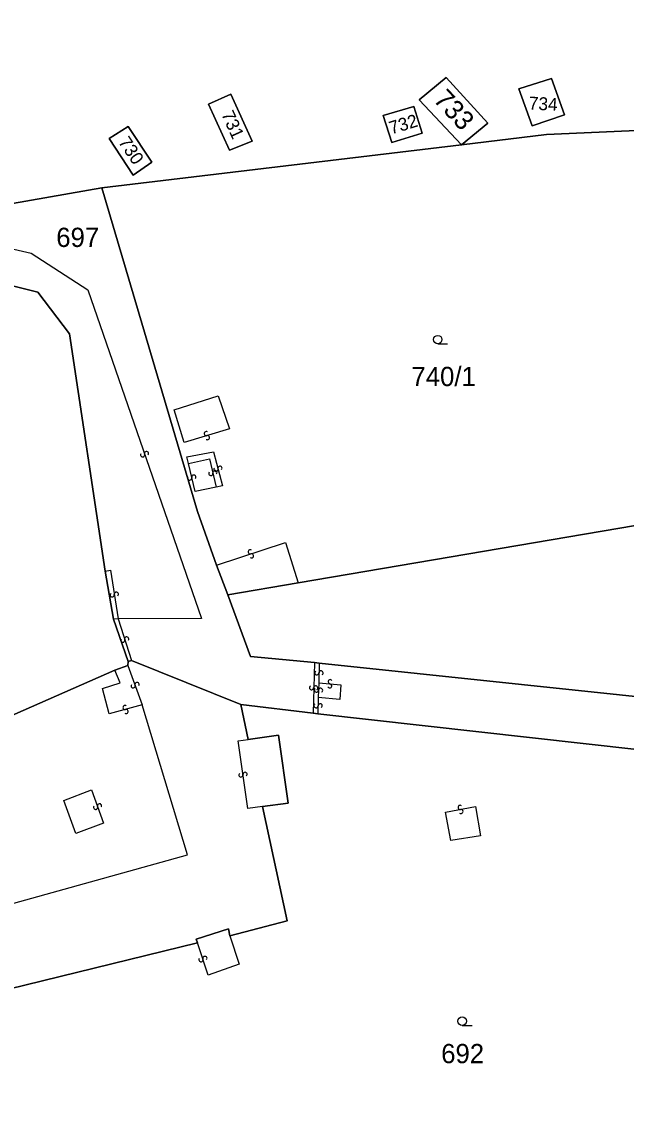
# Model space of a CAD drawing. Extents: x -600309 to -598967, y -1161267 to -1160292.
# Drawn here: x -599586.3 to -599532.9, y -1160977.1 to -1160881.2 of the extents above; entities that cross this region are included whole.
import ezdxf

# ---------------------------------------------------------------- set-up
doc = ezdxf.new("R2010")
doc.units = 0
for name, color, linetype in [('Level 1', 7, 'Continuous'), ('Level 13', 7, 'Continuous'), ('Level 3', 7, 'Continuous'), ('Level 4', 7, 'Continuous'), ('Level 5', 7, 'Continuous'), ('Level 60', 7, 'Continuous')]:
    doc.layers.add(name, color=color, linetype=linetype)

msp = doc.modelspace()

# ---------------------------------------------------------------- linework, layer by layer
at = {"layer": 'Level 1'}
for points in [[(-599547.45, -1160892.09), (-599551.17, -1160888.12), (-599548.78, -1160886.13), (-599545.11, -1160890.17), (-599547.45, -1160892.09)], [(-599542.37, -1160887.15), (-599539.48, -1160886.23), (-599538.32, -1160889.44), (-599541.2, -1160890.42), (-599542.37, -1160887.15)], [(-599569.81, -1160888.5), (-599567.83, -1160887.62), (-599565.94, -1160891.75), (-599567.94, -1160892.55), (-599569.81, -1160888.5)], [(-599554.37, -1160889.51), (-599551.65, -1160888.7), (-599550.92, -1160891.06), (-599553.6, -1160891.87), (-599554.37, -1160889.51)], [(-599578.59, -1160891.52), (-599576.92, -1160890.46), (-599574.82, -1160893.63), (-599576.47, -1160894.77), (-599578.59, -1160891.52)], [(-599521.99, -1160890.39), (-599539.93, -1160891.17), (-599547.45, -1160892.09)], [(-599579.23, -1160895.89), (-599547.45, -1160892.09)], [(-599627.26, -1160901.81), (-599623.88, -1160902.01), (-599610.7, -1160901.38), (-599579.23, -1160895.89)], [(-599579.23, -1160895.89), (-599570.78, -1160924.47), (-599569.11, -1160929.21)], [(-599603.7, -1160903.64), (-599590.9, -1160903.6), (-599584.9, -1160905.11), (-599582.1, -1160908.78), (-599578.94, -1160929.75)], [(-599516.72, -1160923.57), (-599524.58, -1160924.44), (-599561.87, -1160930.78)], [(-599578.94, -1160929.75), (-599578.2, -1160933.98)], [(-599569.11, -1160929.21), (-599568.09, -1160931.83)], [(-599561.87, -1160930.78), (-599568.09, -1160931.83)], [(-599568.09, -1160931.83), (-599566.1, -1160937.3), (-599560.45, -1160937.81)], [(-599578.2, -1160933.98), (-599576.9, -1160937.73)], [(-599576.9, -1160937.73), (-599576.62, -1160937.63)], [(-599576.62, -1160937.63), (-599566.95, -1160941.53)], [(-599626.19, -1160957.49), (-599625.56, -1160959.35), (-599578.08, -1160938.49)], [(-599578.08, -1160938.49), (-599576.93, -1160938.08)], [(-599576.93, -1160938.08), (-599576.9, -1160937.73)], [(-599560.45, -1160937.81), (-599560.03, -1160937.87)], [(-599560.03, -1160937.87), (-599489, -1160945.35), (-599487.6, -1160945.48)], [(-599566.3, -1160944.61), (-599566.95, -1160941.53)], [(-599566.95, -1160941.53), (-599560.56, -1160942.31)], [(-599560.56, -1160942.31), (-599560.13, -1160942.37)], [(-599560.13, -1160942.37), (-599489.23, -1160950.29)], [(-599565.04, -1160950.54), (-599562.75, -1160950.25), (-599563.61, -1160944.23), (-599566.3, -1160944.61)], [(-599567.91, -1160961.97), (-599562.84, -1160960.63), (-599565.04, -1160950.54)], [(-599570.78, -1160962.58), (-599570.9, -1160962.27), (-599568.04, -1160961.36), (-599567.91, -1160961.97)], [(-599634.03, -1160961.92), (-599630.1, -1160977.09), (-599570.78, -1160962.58)]]:
    msp.add_lwpolyline(points, dxfattribs=at)
at = {"layer": 'Level 13'}
for centre, start, end in [((-599570.012, -1160917.603), 53.85752, 286.44752), ((-599569.909, -1160917.957), 234.07198, 106.16998), ((-599575.634, -1160919.479), 146.20637, 18.79637), ((-599575.285, -1160919.361), 326.42083, 198.51882), ((-599571.111, -1160921.439), 320.37294, 192.96294), ((-599569.599, -1160921.121), 140.21983, 12.80983), ((-599569.24, -1160921.04), 320.43428, 192.53228), ((-599569.148, -1160920.757), 142.13739, 14.72739), ((-599568.791, -1160920.664), 322.35185, 194.44984), ((-599571.47, -1160921.521), 140.58739, 12.68539), ((-599566.115, -1160928.044), 55.35565, 287.45365), ((-599566.004, -1160928.395), 235.1412, 107.7312), ((-599578.322, -1160931.848), 136.01455, 8.60455), ((-599577.957, -1160931.793), 316.229, 188.327), ((-599577.395, -1160935.856), 145.16952, 17.75952), ((-599577.044, -1160935.745), 325.38398, 197.48197), ((-599560.224, -1160938.738), 126.82899, 359.41899), ((-599559.856, -1160938.743), 307.04345, 179.14145), ((-599576.126, -1160939.759), 327.27648, 199.37448), ((-599559.05, -1160939.517), 31.77913, 263.87713), ((-599576.473, -1160939.882), 147.06203, 19.65203), ((-599560.694, -1160940.055), 125.75799, 358.34799), ((-599560.326, -1160940.066), 305.97245, 178.07045), ((-599560.264, -1160940.258), 123.66364, 356.25364), ((-599559.896, -1160940.283), 303.87809, 175.97609), ((-599559.089, -1160939.883), 211.56468, 84.15468), ((-599560.304, -1160941.638), 126.76314, 359.35314), ((-599559.936, -1160941.643), 306.9776, 179.07559), ((-599577.188, -1160941.792), 52.61177, 285.20177), ((-599577.092, -1160942.148), 232.82622, 104.92422), ((-599566.943, -1160947.754), 135.44926, 7.54726), ((-599566.578, -1160947.705), 315.23481, 187.82481), ((-599579.793, -1160950.613), 147.50045, 20.09045), ((-599579.446, -1160950.487), 327.71491, 199.81291), ((-599547.553, -1160950.618), 48.05764, 280.15564), ((-599547.487, -1160950.981), 227.84319, 100.43319), ((-599570.476, -1160964.076), 145.68782, 17.78581), ((-599570.125, -1160963.963), 325.47336, 198.06336)]:
    msp.add_arc(centre, 0.184, start, end, dxfattribs=at)
at = {"layer": 'Level 3'}
for points in [[(-599603.7, -1160903.64), (-599590.88, -1160900.42), (-599585.5, -1160901.67), (-599580.47, -1160904.89), (-599570.44, -1160933.94), (-599577.81, -1160933.97)], [(-599572.85, -1160915.49), (-599568.95, -1160914.26), (-599567.96, -1160917.18), (-599571.96, -1160918.38), (-599572.85, -1160915.49)], [(-599571.58, -1160920.25), (-599571.73, -1160919.65), (-599569.37, -1160919.22), (-599568.57, -1160922.21), (-599569.13, -1160922.33)], [(-599571.58, -1160920.25), (-599569.71, -1160919.83), (-599569.13, -1160922.33)], [(-599569.13, -1160922.33), (-599571, -1160922.72), (-599571.58, -1160920.25)], [(-599569.11, -1160929.21), (-599563.01, -1160927.23), (-599561.87, -1160930.78)], [(-599578.94, -1160929.75), (-599578.48, -1160929.67), (-599577.81, -1160933.97)], [(-599577.81, -1160933.97), (-599578.2, -1160933.98)], [(-599577.81, -1160933.97), (-599576.62, -1160937.63)], [(-599575.67, -1160941.56), (-599578.6, -1160942.37), (-599579.18, -1160940.13), (-599577.61, -1160939.61), (-599578.08, -1160938.49)], [(-599576.93, -1160938.08), (-599575.67, -1160941.56)], [(-599560.45, -1160937.81), (-599560.56, -1160942.31)], [(-599560.03, -1160937.87), (-599560.04, -1160939.61)], [(-599560.04, -1160939.61), (-599560.12, -1160940.92)], [(-599560.04, -1160939.61), (-599558.1, -1160939.8), (-599558.21, -1160941.08), (-599560.12, -1160940.92)], [(-599560.12, -1160940.92), (-599560.13, -1160942.37)], [(-599628.43, -1160960.35), (-599626.01, -1160969.92), (-599571.68, -1160954.82), (-599575.67, -1160941.56)], [(-599565.04, -1160950.54), (-599566.34, -1160950.73), (-599567.19, -1160944.74), (-599566.3, -1160944.61)], [(-599582.61, -1160950.01), (-599580.17, -1160949.08), (-599579.08, -1160952.02), (-599581.54, -1160952.93), (-599582.61, -1160950.01)], [(-599548.85, -1160951.05), (-599546.2, -1160950.55), (-599545.76, -1160953.13), (-599548.38, -1160953.56), (-599548.85, -1160951.05)], [(-599567.91, -1160961.97), (-599567.1, -1160964.46), (-599569.83, -1160965.45), (-599570.78, -1160962.58)]]:
    msp.add_lwpolyline(points, dxfattribs=at)
at = {"layer": 'Level 5'}
for p, q in [((-599549.54, -1160909.67), (-599548.665, -1160909.67)), ((-599547.38, -1160969.88), (-599546.505, -1160969.88))]:
    msp.add_line(p, q, dxfattribs=at)
for centre in [(-599549.54, -1160909.295), (-599547.38, -1160969.505)]:
    msp.add_circle(centre, 0.375, dxfattribs=at)
at = {"layer": 'Level 60'}
for points in [[(-599485.56, -1160874.64), (-599479.62, -1160886.55), (-599478.75, -1160888.22), (-599488.46, -1160888.93), (-599521.99, -1160890.39), (-599539.93, -1160891.17), (-599547.45, -1160892.09), (-599545.11, -1160890.17), (-599548.78, -1160886.13), (-599551.17, -1160888.12), (-599547.45, -1160892.09), (-599579.23, -1160895.89), (-599610.7, -1160901.38), (-599623.88, -1160902.01), (-599627.26, -1160901.81), (-599623.8, -1160900.4), (-599625.9, -1160895.19), (-599629.23, -1160896.54), (-599627.26, -1160901.81), (-599628.39, -1160901.69), (-599634.95, -1160898.11), (-599638.48, -1160895.36), (-599648.13, -1160877.1)], [(-599610.7, -1160901.38), (-599579.23, -1160895.89), (-599570.78, -1160924.47), (-599569.11, -1160929.21), (-599568.09, -1160931.83), (-599566.1, -1160937.3), (-599560.45, -1160937.81), (-599560.03, -1160937.87), (-599489, -1160945.35), (-599487.6, -1160945.48), (-599486.18, -1160950.38), (-599489.23, -1160950.29), (-599560.13, -1160942.37), (-599560.56, -1160942.31), (-599566.95, -1160941.53), (-599576.62, -1160937.63), (-599576.9, -1160937.73), (-599578.2, -1160933.98), (-599578.94, -1160929.75), (-599582.1, -1160908.78), (-599584.9, -1160905.11), (-599590.9, -1160903.6)], [(-599630.1, -1160977.09), (-599570.78, -1160962.58), (-599570.9, -1160962.27), (-599568.04, -1160961.36), (-599567.91, -1160961.97), (-599562.84, -1160960.63), (-599565.04, -1160950.54), (-599562.75, -1160950.25), (-599563.61, -1160944.23), (-599566.3, -1160944.61), (-599566.95, -1160941.53), (-599560.56, -1160942.31), (-599560.13, -1160942.37), (-599489.23, -1160950.29), (-599486.18, -1160950.38), (-599482.56, -1160962.83), (-599483.73, -1160963.17), (-599483.91, -1160963.63), (-599488.59, -1160964.84), (-599490.61, -1160965.36), (-599512.52, -1160979.46), (-599599.9, -1161001.22)]]:
    msp.add_lwpolyline(points, dxfattribs=at)
for points in [[(-599551.17, -1160888.12), (-599548.78, -1160886.13), (-599545.11, -1160890.17), (-599547.45, -1160892.09)], [(-599539.48, -1160886.23), (-599542.37, -1160887.15), (-599541.2, -1160890.42), (-599538.32, -1160889.44)], [(-599542.37, -1160887.15), (-599539.48, -1160886.23), (-599538.32, -1160889.44), (-599541.2, -1160890.42)], [(-599567.83, -1160887.62), (-599569.81, -1160888.5), (-599567.94, -1160892.55), (-599565.94, -1160891.75)], [(-599569.81, -1160888.5), (-599567.83, -1160887.62), (-599565.94, -1160891.75), (-599567.94, -1160892.55)], [(-599551.65, -1160888.7), (-599554.37, -1160889.51), (-599553.6, -1160891.87), (-599550.92, -1160891.06)], [(-599554.37, -1160889.51), (-599551.65, -1160888.7), (-599550.92, -1160891.06), (-599553.6, -1160891.87)], [(-599539.93, -1160891.17), (-599521.99, -1160890.39), (-599521.35, -1160893.62), (-599521.33, -1160895.2), (-599527.88, -1160900.38), (-599531.85, -1160902.49), (-599528.61, -1160910.91), (-599525.31, -1160914.64), (-599522.65, -1160919.14), (-599518.88, -1160918.13), (-599516.72, -1160923.57), (-599524.58, -1160924.44), (-599561.87, -1160930.78), (-599568.09, -1160931.83), (-599569.11, -1160929.21), (-599570.78, -1160924.47), (-599579.23, -1160895.89), (-599547.45, -1160892.09)], [(-599576.92, -1160890.46), (-599578.59, -1160891.52), (-599576.47, -1160894.77), (-599574.82, -1160893.63)], [(-599578.59, -1160891.52), (-599576.92, -1160890.46), (-599574.82, -1160893.63), (-599576.47, -1160894.77)], [(-599626.19, -1160957.49), (-599627.04, -1160955.29), (-599627.49, -1160954.09), (-599628, -1160952.78), (-599631.09, -1160944.51), (-599631.51, -1160943.39), (-599634.82, -1160934.77), (-599602.39, -1160921.75), (-599606.74, -1160909.54), (-599607.78, -1160908.07), (-599609.31, -1160907.02), (-599610.98, -1160906.27), (-599612.63, -1160906.07), (-599613.95, -1160906.13), (-599603.7, -1160903.64), (-599590.9, -1160903.6), (-599584.9, -1160905.11), (-599582.1, -1160908.78), (-599578.94, -1160929.75), (-599578.2, -1160933.98), (-599576.9, -1160937.73), (-599576.93, -1160938.08), (-599578.08, -1160938.49), (-599625.56, -1160959.35)], [(-599566.1, -1160937.3), (-599568.09, -1160931.83), (-599561.87, -1160930.78), (-599524.58, -1160924.44), (-599516.72, -1160923.57), (-599479.39, -1160919.42), (-599479.09, -1160925.54), (-599483.59, -1160926.84), (-599481.91, -1160932.72), (-599482.75, -1160932.96), (-599482.33, -1160934.41), (-599481.37, -1160934.13), (-599480.29, -1160938.1), (-599480.15, -1160938.6), (-599488.87, -1160941.13), (-599487.6, -1160945.48), (-599489, -1160945.35), (-599560.03, -1160937.87), (-599560.45, -1160937.81)], [(-599630.1, -1160977.09), (-599634.03, -1160961.92), (-599628.43, -1160960.35), (-599628.51, -1160958.26), (-599629.37, -1160956.12), (-599627.04, -1160955.29), (-599626.19, -1160957.49), (-599625.56, -1160959.35), (-599578.08, -1160938.49), (-599576.93, -1160938.08), (-599576.9, -1160937.73), (-599576.62, -1160937.63), (-599566.95, -1160941.53), (-599566.3, -1160944.61), (-599563.61, -1160944.23), (-599562.75, -1160950.25), (-599565.04, -1160950.54), (-599562.84, -1160960.63), (-599567.91, -1160961.97), (-599568.04, -1160961.36), (-599570.9, -1160962.27), (-599570.78, -1160962.58)]]:
    msp.add_lwpolyline(points, close=True, dxfattribs=at)

# ---------------------------------------------------------------- texts
at = {"layer": 'Level 4'}
for s, height, rotation, p in [('733', 1.7, 312.81678, (-599549.992, -1160888.159)), ('734', 1.14, 357.01137, (-599541.505, -1160888.959)), ('731', 1.14, 294.29388, (-599568.7, -1160889.374)), ('732', 1.14, 16.99083, (-599553.637, -1160891.177)), ('730', 1.14, 304.01937, (-599577.827, -1160891.841))]:
    msp.add_text(s, height=height, rotation=rotation, dxfattribs=at).set_placement(p)
for s, p in [('697', (-599583.27, -1160901.11)), ('740/1', (-599551.86, -1160913.4)), ('692', (-599549.23, -1160973.22))]:
    msp.add_text(s, height=1.7, dxfattribs=at).set_placement(p)

doc.saveas('drawing.dxf')
